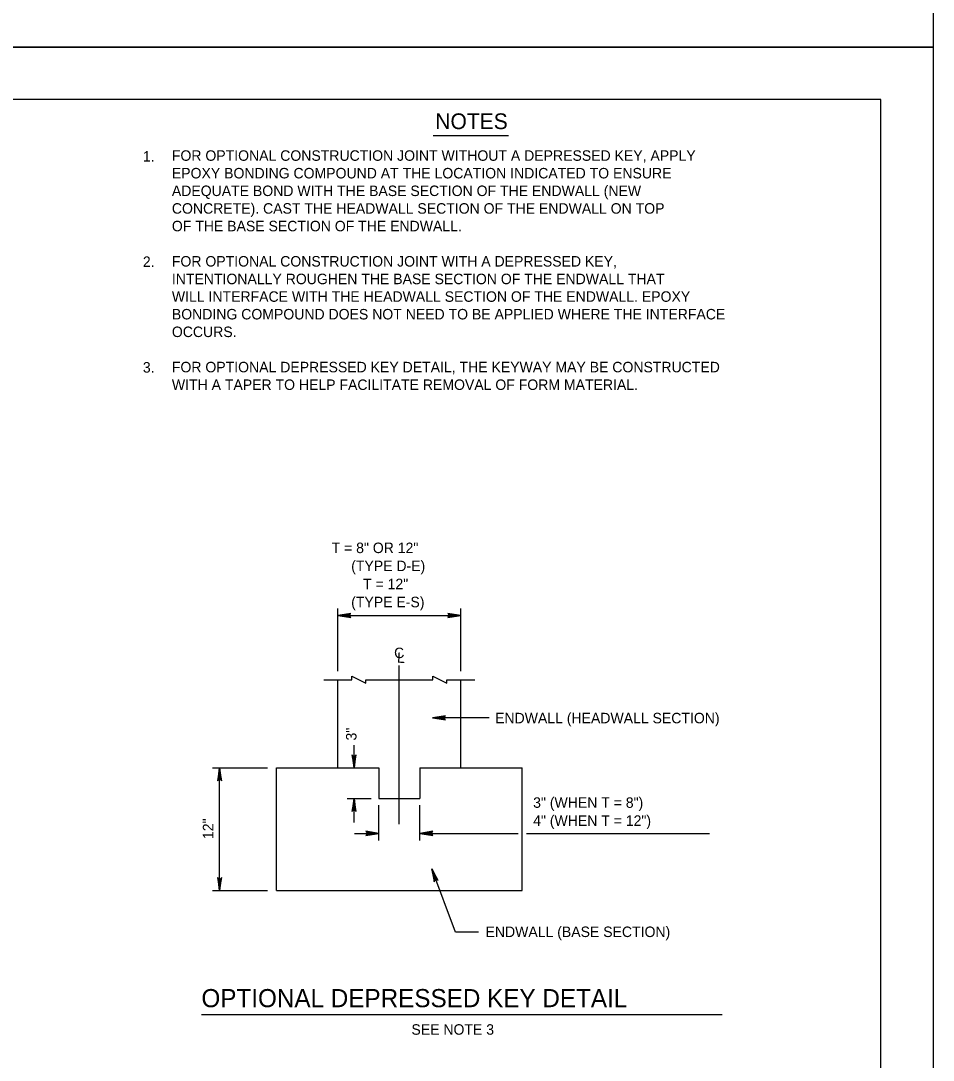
# Model space of a CAD drawing. Extents: x 638877 to 639960, y 297341 to 299123.
# Drawn here: x 639457.3 to 639718.2, y 298239.6 to 298536.8 of the extents above; entities that cross this region are included whole.
import ezdxf

# ---------------------------------------------------------------- set-up
doc = ezdxf.new("R2010")
doc.units = 0
for name, color, linetype in [('1', 7, 'Continuous'), ('2', 7, 'Continuous'), ('3', 7, 'Continuous'), ('PLT-BNDY', 7, 'Continuous')]:
    doc.layers.add(name, color=color, linetype=linetype)

msp = doc.modelspace()

# ---------------------------------------------------------------- linework, layer by layer
at = {"layer": '1'}
for p, q in [((639703.19, 298514.28), (638917.19, 298514.28)), ((639703.19, 297950.28), (639703.19, 298514.28)), ((639575.2, 298503.96), (639596.75, 298503.96)), ((639565.51, 298307.05), (639565.51, 298352.48))]:
    msp.add_line(p, q, dxfattribs=at)
at = {"layer": '2'}
for p, q in [((639547.96, 298350.85), (639547.96, 298368.73)), ((639547.96, 298366.73), (639583.06, 298366.73)), ((639583.06, 298350.85), (639583.06, 298368.73)), ((639551.96, 298348.39), (639551.96, 298349.39)), ((639551.96, 298349.39), (639555.96, 298347.39)), ((639575.06, 298348.39), (639575.06, 298349.39)), ((639575.06, 298349.39), (639579.06, 298347.39)), ((639543.96, 298348.39), (639551.96, 298348.39)), ((639547.96, 298323.16), (639547.96, 298348.39)), ((639555.96, 298347.39), (639555.96, 298348.39)), ((639555.96, 298348.39), (639575.06, 298348.39)), ((639579.06, 298348.39), (639587.06, 298348.39)), ((639579.06, 298347.39), (639579.06, 298348.39)), ((639583.06, 298323.16), (639583.06, 298348.39)), ((639591.18, 298337.45), (639574.96, 298337.45)), ((639552.56, 298323.16), (639552.56, 298329.66)), ((639512.13, 298323.16), (639527.81, 298323.16)), ((639514.13, 298288.06), (639514.13, 298323.16)), ((639530.41, 298288.06), (639530.41, 298323.16)), ((639530.41, 298323.16), (639559.66, 298323.16)), ((639559.66, 298323.16), (639559.66, 298314.38)), ((639571.36, 298323.16), (639571.36, 298314.38)), ((639571.36, 298323.16), (639600.61, 298323.16)), ((639600.61, 298288.06), (639600.61, 298323.16)), ((639550.56, 298314.38), (639557.5, 298314.38)), ((639552.56, 298307.59), (639552.56, 298314.38)), ((639559.66, 298314.38), (639571.36, 298314.38)), ((639559.66, 298302.44), (639559.66, 298312.47)), ((639571.36, 298302.44), (639571.36, 298312.47)), ((639552.72, 298304.44), (639559.66, 298304.44)), ((639571.36, 298304.44), (639599.45, 298304.44)), ((639601.91, 298304.44), (639654.19, 298304.44)), ((639581.53, 298276.22), (639574.77, 298294.3)), ((639512.13, 298288.06), (639527.81, 298288.06)), ((639530.41, 298288.06), (639600.61, 298288.06)), ((639588.11, 298276.22), (639581.53, 298276.22))]:
    msp.add_line(p, q, dxfattribs=at)
for points in [[(639551.5, 298367.18), (639551.37, 298366.92), (639547.96, 298366.73), (639551.5, 298367.18), (639551.68, 298367.34), (639547.96, 298366.73), (639551.37, 298366.57), (639551.49, 298366.31), (639547.96, 298366.73), (639551.68, 298366.14), (639551.49, 298366.31)], [(639579.52, 298366.29), (639579.65, 298366.55), (639583.06, 298366.73), (639579.52, 298366.29), (639579.34, 298366.13), (639583.06, 298366.73), (639579.65, 298366.9), (639579.53, 298367.16), (639583.06, 298366.73), (639579.34, 298367.33), (639579.53, 298367.16)], [(639578.5, 298337.91), (639578.36, 298337.65), (639574.96, 298337.46), (639578.5, 298337.91), (639578.68, 298338.06), (639574.96, 298337.46), (639578.36, 298337.29), (639578.49, 298337.04), (639574.96, 298337.46), (639578.68, 298336.87), (639578.49, 298337.04)], [(639552.12, 298326.7), (639552.38, 298326.56), (639552.56, 298323.16), (639552.12, 298326.7), (639551.96, 298326.88), (639552.56, 298323.16), (639552.73, 298326.56), (639552.98, 298326.69), (639552.56, 298323.16), (639553.16, 298326.88), (639552.98, 298326.69)], [(639514.58, 298319.62), (639514.32, 298319.75), (639514.13, 298323.16), (639514.58, 298319.62), (639514.73, 298319.43), (639514.13, 298323.16), (639513.96, 298319.75), (639513.71, 298319.63), (639514.13, 298323.16), (639513.54, 298319.43), (639513.71, 298319.63)], [(639553.01, 298310.84), (639552.75, 298310.97), (639552.56, 298314.38), (639553.01, 298310.84), (639553.16, 298310.66), (639552.56, 298314.38), (639552.39, 298310.98), (639552.14, 298310.85), (639552.56, 298314.38), (639551.97, 298310.66), (639552.14, 298310.85)], [(639556.12, 298304), (639556.25, 298304.25), (639559.66, 298304.44), (639556.12, 298304), (639555.94, 298303.84), (639559.66, 298304.44), (639556.25, 298304.61), (639556.13, 298304.86), (639559.66, 298304.44), (639555.94, 298305.03), (639556.13, 298304.86)], [(639574.9, 298304.89), (639574.77, 298304.63), (639571.36, 298304.44), (639574.9, 298304.89), (639575.08, 298305.04), (639571.36, 298304.44), (639574.77, 298304.27), (639574.89, 298304.02), (639571.36, 298304.44), (639575.08, 298303.85), (639574.89, 298304.02)], [(639576.41, 298291.13), (639576.13, 298291.17), (639574.77, 298294.3), (639576.41, 298291.13), (639576.62, 298291.01), (639574.77, 298294.3), (639575.79, 298291.04), (639575.6, 298290.84), (639574.77, 298294.3), (639575.5, 298290.6), (639575.6, 298290.84)], [(639513.68, 298291.6), (639513.94, 298291.46), (639514.13, 298288.06), (639513.68, 298291.6), (639513.53, 298291.78), (639514.13, 298288.06), (639514.29, 298291.46), (639514.55, 298291.59), (639514.13, 298288.06), (639514.72, 298291.78), (639514.55, 298291.59)]]:
    msp.add_lwpolyline(points, dxfattribs=at)
at = {"layer": '3'}
msp.add_line((639508.92, 298252.63), (639657.84, 298252.63), dxfattribs=at)
at = {"layer": 'PLT-BNDY'}
for points in [[(638877.19, 299123.28), (639718.19, 299123.28), (639718.19, 298529.28), (638877.19, 298529.28)], [(638877.19, 298529.28), (639718.19, 298529.28), (639718.19, 297935.28), (638877.19, 297935.28)]]:
    msp.add_lwpolyline(points, close=True, dxfattribs=at)

# ---------------------------------------------------------------- texts
at = {"layer": '1'}
for s, p in [('FOR OPTIONAL CONSTRUCTION JOINT WITHOUT A DEPRESSED KEY, APPLY ', (639500.47, 298496.75)), ('EPOXY BONDING COMPOUND AT THE LOCATION INDICATED TO ENSURE ', (639500.47, 298491.71)), ('ADEQUATE BOND WITH THE BASE SECTION OF THE ENDWALL (NEW ', (639500.47, 298486.67)), ('CONCRETE). CAST THE HEADWALL SECTION OF THE ENDWALL ON TOP ', (639500.47, 298481.63)), ('OF THE BASE SECTION OF THE ENDWALL. ', (639500.47, 298476.59)), ('FOR OPTIONAL CONSTRUCTION JOINT WITH A DEPRESSED KEY, ', (639500.47, 298466.51)), ('INTENTIONALLY ROUGHEN THE BASE SECTION OF THE ENDWALL THAT ', (639500.47, 298461.47)), ('WILL INTERFACE WITH THE HEADWALL SECTION OF THE ENDWALL. EPOXY', (639500.47, 298456.43)), ('BONDING COMPOUND DOES NOT NEED TO BE APPLIED WHERE THE INTERFACE', (639500.47, 298451.39)), ('OCCURS.', (639500.47, 298446.35)), ('FOR OPTIONAL DEPRESSED KEY DETAIL, THE KEYWAY MAY BE CONSTRUCTED', (639500.47, 298436.27)), ('WITH A TAPER TO HELP FACILITATE REMOVAL OF FORM MATERIAL.', (639500.47, 298431.23))]:
    msp.add_text(s, height=3, dxfattribs=at).set_placement(p)
for s, rotation, p in [('C', 5, (639564.16, 298354.42)), ('L', 357, (639564.8, 298353.26))]:
    msp.add_text(s, height=3, rotation=rotation, dxfattribs=at).set_placement(p)
at = {"layer": '3'}
for s, height, p in [('NOTES', 4.5, (639575.79, 298505.81)), ('1.  ', 3, (639492.17, 298496.52)), ('2.  ', 3, (639492.17, 298466.4)), ('3.  ', 3, (639492.17, 298436.19)), ('T = 8" OR 12"', 2.9999, (639546.14, 298384.58)), ('(TYPE D-E)', 3, (639551.75, 298379.42)), ('T = 12"', 3, (639555.14, 298374.26)), ('(TYPE E-S)', 3, (639551.75, 298369.1)), ('ENDWALL (HEADWALL SECTION)', 2.9999, (639592.9, 298335.91)), ('3" (WHEN T = 8")', 2.9999, (639603.78, 298311.75)), ('4" (WHEN T = 12")', 2.9999, (639603.78, 298306.59)), ('ENDWALL (BASE SECTION)', 2.9999, (639590.16, 298274.8)), ('OPTIONAL DEPRESSED KEY DETAIL', 5.1858, (639508.92, 298254.74)), ('SEE NOTE 3', 3, (639568.97, 298246.87))]:
    msp.add_text(s, height=height, dxfattribs=at).set_placement(p)
for s, p in [('3"', (639553.27, 298331)), ('12"', (639512.32, 298302.82))]:
    msp.add_text(s, height=3, rotation=90, dxfattribs=at).set_placement(p)

doc.saveas('drawing.dxf')
